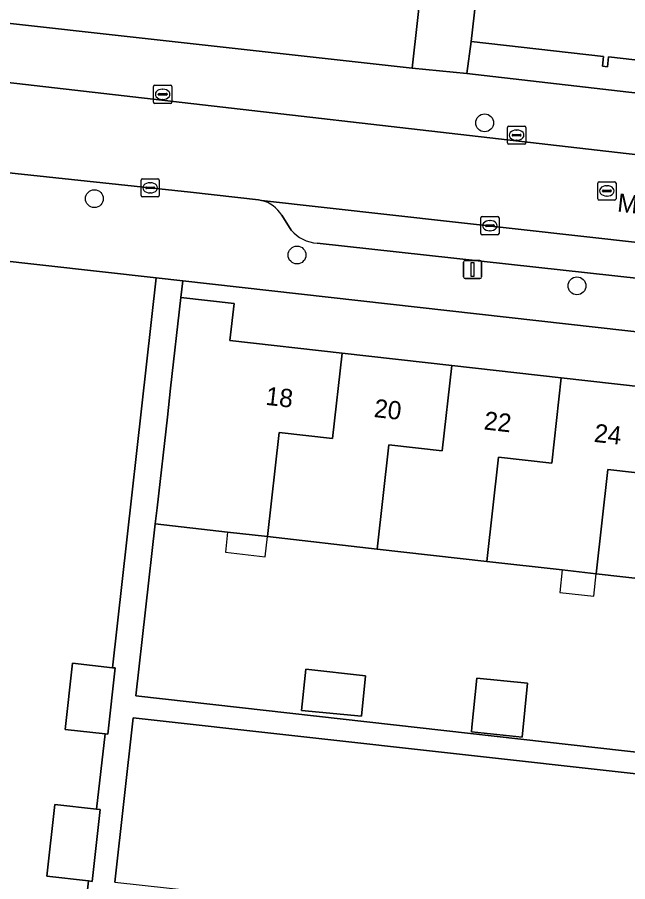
# Model space of a CAD drawing. Extents: x 162082 to 163401, y 388089 to 388636.
# Drawn here: x 162681.06 to 162714.51, y 388132.52 to 388179.87 of the extents above; entities that cross this region are included whole.
import ezdxf

# ---------------------------------------------------------------- set-up
doc = ezdxf.new("R2010")
doc.units = 0
for name, color, linetype in [('IMGEO_Boom', 7, 'Continuous'), ('IMGEO_Erf', 7, 'Continuous'), ('IMGEO_Groenvoorziening', 7, 'Continuous'), ('IMGEO_Kolk', 7, 'Continuous'), ('IMGEO_Lichtmast', 7, 'Continuous'), ('IMGEO_Openbare_ruimte_label', 7, 'Continuous'), ('IMGEO_Pand', 7, 'Continuous'), ('IMGEO_Pand_nummerreeks', 7, 'Continuous'), ('IMGEO_Pand_overbouw', 7, 'Continuous'), ('IMGEO_Parkeervlak_open', 7, 'Continuous'), ('IMGEO_Rijbaan_lokaal_open', 7, 'Continuous'), ('IMGEO_Rioolput', 7, 'Continuous'), ('IMGEO_Voetpad_open', 7, 'Continuous')]:
    doc.layers.add(name, color=color, linetype=linetype)

msp = doc.modelspace()

# ---------------------------------------------------------------- linework, layer by layer
at = {"layer": 'IMGEO_Boom'}
for centre in [(162706.672, 388174.085), (162685.288, 388169.933), (162696.391, 388166.846), (162711.731, 388165.158)]:
    msp.add_circle(centre, 0.489, dxfattribs=at)
at = {"layer": 'IMGEO_Erf'}
for points in [[(162717.454, 388177.245), (162713.462, 388177.697), (162713.4, 388177.152), (162713.124, 388177.183), (162713.185, 388177.719), (162705.936, 388178.541), (162705.689, 388176.792), (162763.406, 388170.138)], [(162684.587, 388129.167), (162684.969, 388132.561), (162682.683, 388132.816), (162683.123, 388136.749), (162685.41, 388136.493), (162685.873, 388140.615), (162683.681, 388140.86), (162684.087, 388144.488), (162686.28, 388144.243), (162688.677, 388165.591), (162664.145, 388168.344)]]:
    msp.add_lwpolyline(points, dxfattribs=at)
for points in [[(162690.136, 388165.428), (162690.025, 388164.519), (162692.944, 388164.19), (162692.715, 388162.163), (162698.866, 388161.469), (162704.866, 388160.792), (162710.866, 388160.116), (162716.866, 388159.439), (162722.866, 388158.762), (162728.866, 388158.085), (162734.867, 388157.408), (162740.866, 388156.732), (162746.866, 388156.055), (162753.017, 388155.361), (162753.371, 388158.332)], [(162724.791, 388148.035), (162718.788, 388148.712), (162712.786, 388149.389), (162710.922, 388149.599), (162706.783, 388150.066), (162700.78, 388150.743), (162694.777, 388151.42), (162692.591, 388151.667), (162688.625, 388152.114), (162687.557, 388142.698), (162750.849, 388135.576), (162751.105, 388137.978), (162751.921, 388145.652), (162749.019, 388145.98), (162748.944, 388145.311), (162743.976, 388145.871), (162742.794, 388146.004), (162736.796, 388146.681), (162730.793, 388147.358)], [(162700.152, 388143.803), (162699.931, 388141.582), (162696.629, 388141.897), (162696.872, 388144.159)], [(162709.02, 388143.398), (162708.726, 388140.444), (162705.952, 388140.72), (162705.978, 388140.981), (162706.246, 388143.674)], [(162686.416, 388132.5), (162692.567, 388131.812), (162698.577, 388131.139), (162704.584, 388130.467), (162710.59, 388129.795), (162716.595, 388129.123), (162722.602, 388128.45), (162728.607, 388127.778), (162734.613, 388127.106), (162740.619, 388126.434), (162741.808, 388126.301), (162746.777, 388125.745), (162749.751, 388125.412), (162750.72, 388134.36), (162750.73, 388134.453), (162687.422, 388141.491)]]:
    msp.add_lwpolyline(points, close=True, dxfattribs=at)
at = {"layer": 'IMGEO_Groenvoorziening'}
msp.add_lwpolyline([(162703.27, 388182.157), (162665.601, 388186.69), (162665.064, 388181.271), (162702.709, 388177.08)], close=True, dxfattribs=at)
at = {"layer": 'IMGEO_Kolk'}
for p, q in [((162688.529, 388175.224), (162688.529, 388176.076)), ((162688.604, 388176.15), (162689.456, 388176.15)), ((162689.53, 388176.076), (162689.53, 388175.224)), ((162688.788, 388175.644), (162688.788, 388175.656)), ((162689.226, 388175.607), (162688.828, 388175.607)), ((162688.831, 388175.693), (162689.229, 388175.693)), ((162689.017, 388175.93), (162689.042, 388175.93)), ((162689.272, 388175.656), (162689.272, 388175.644)), ((162689.456, 388175.15), (162688.604, 388175.15)), ((162689.04, 388175.37), (162689.015, 388175.37)), ((162707.923, 388172.985), (162707.923, 388173.837)), ((162707.998, 388173.911), (162708.85, 388173.911)), ((162708.411, 388173.691), (162708.436, 388173.691)), ((162708.924, 388173.837), (162708.924, 388172.985)), ((162708.182, 388173.405), (162708.182, 388173.417)), ((162708.62, 388173.368), (162708.222, 388173.368)), ((162708.225, 388173.454), (162708.623, 388173.454)), ((162708.666, 388173.417), (162708.666, 388173.405)), ((162708.85, 388172.911), (162707.998, 388172.911)), ((162708.434, 388173.131), (162708.409, 388173.131)), ((162687.845, 388170.1), (162687.845, 388170.952)), ((162687.92, 388171.026), (162688.772, 388171.026)), ((162688.846, 388170.952), (162688.846, 388170.1)), ((162688.104, 388170.52), (162688.104, 388170.532)), ((162688.542, 388170.483), (162688.144, 388170.483)), ((162688.147, 388170.569), (162688.545, 388170.569)), ((162688.333, 388170.806), (162688.358, 388170.806)), ((162688.588, 388170.532), (162688.588, 388170.52)), ((162688.772, 388170.026), (162687.92, 388170.026)), ((162688.356, 388170.246), (162688.331, 388170.246)), ((162706.533, 388168.954), (162707.385, 388168.954)), ((162706.458, 388168.028), (162706.458, 388168.88)), ((162706.717, 388168.448), (162706.717, 388168.46)), ((162706.76, 388168.497), (162707.158, 388168.497)), ((162706.946, 388168.734), (162706.971, 388168.734)), ((162707.201, 388168.46), (162707.201, 388168.448)), ((162707.459, 388168.88), (162707.459, 388168.028)), ((162707.155, 388168.411), (162706.757, 388168.411)), ((162706.969, 388168.174), (162706.944, 388168.174)), ((162707.385, 388167.954), (162706.533, 388167.954))]:
    msp.add_line(p, q, dxfattribs=at)
for points in [[(162688.529, 388175.224), (162688.529, 388176.076)], [(162688.604, 388176.15), (162689.456, 388176.15)], [(162689.53, 388176.076), (162689.53, 388175.224)], [(162689.456, 388175.15), (162688.604, 388175.15)], [(162707.923, 388172.985), (162707.923, 388173.837)], [(162707.998, 388173.911), (162708.85, 388173.911)], [(162708.924, 388173.837), (162708.924, 388172.985)], [(162708.85, 388172.911), (162707.998, 388172.911)], [(162687.845, 388170.1), (162687.845, 388170.952)], [(162687.92, 388171.026), (162688.772, 388171.026)], [(162688.846, 388170.952), (162688.846, 388170.1)], [(162688.772, 388170.026), (162687.92, 388170.026)], [(162706.533, 388168.954), (162707.385, 388168.954)], [(162706.458, 388168.028), (162706.458, 388168.88)], [(162707.459, 388168.88), (162707.459, 388168.028)], [(162707.385, 388167.954), (162706.533, 388167.954)]]:
    msp.add_lwpolyline(points, dxfattribs=at)
for centre, radius, start, end in [((162688.606, 388176.074), 0.0765, 91.552, 178.448), ((162688.606, 388176.074), 0.0765, 91.552, 178.448), ((162689.454, 388176.074), 0.0765, 1.552, 88.448), ((162689.454, 388176.074), 0.0765, 1.552, 88.448), ((162688.828, 388175.653), 0.0403, 85.8775, 175.7526), ((162688.825, 388175.643), 0.0366, 178.938, 274.7102), ((162689.229, 388175.65), 0.043, 264.8664, 352.4533), ((162689.233, 388175.655), 0.0386, 1.7309, 96.639), ((162688.606, 388175.226), 0.0765, 181.552, 268.448), ((162688.606, 388175.226), 0.0765, 181.552, 268.448), ((162689.454, 388175.226), 0.0765, 271.552, 358.448), ((162689.454, 388175.226), 0.0765, 271.552, 358.448), ((162708, 388173.835), 0.0765, 91.552, 178.448), ((162708, 388173.835), 0.0765, 91.552, 178.448), ((162708.848, 388173.835), 0.0765, 1.552, 88.448), ((162708.848, 388173.835), 0.0765, 1.552, 88.448), ((162708.222, 388173.414), 0.0403, 85.8775, 175.7526), ((162708.219, 388173.404), 0.0366, 178.938, 274.7102), ((162708.623, 388173.411), 0.043, 264.8664, 352.4533), ((162708.627, 388173.416), 0.0386, 1.7309, 96.639), ((162708, 388172.987), 0.0765, 181.552, 268.448), ((162708, 388172.987), 0.0765, 181.552, 268.448), ((162708.848, 388172.987), 0.0765, 271.552, 358.448), ((162708.848, 388172.987), 0.0765, 271.552, 358.448), ((162687.922, 388170.95), 0.0765, 91.552, 178.448), ((162687.922, 388170.95), 0.0765, 91.552, 178.448), ((162688.77, 388170.95), 0.0765, 1.552, 88.448), ((162688.77, 388170.95), 0.0765, 1.552, 88.448), ((162688.144, 388170.529), 0.0403, 85.8775, 175.7526), ((162688.141, 388170.519), 0.0366, 178.938, 274.7102), ((162688.545, 388170.526), 0.043, 264.8664, 352.4533), ((162688.549, 388170.531), 0.0386, 1.7309, 96.639), ((162687.922, 388170.102), 0.0765, 181.552, 268.448), ((162687.922, 388170.102), 0.0765, 181.552, 268.448), ((162688.77, 388170.102), 0.0765, 271.552, 358.448), ((162688.77, 388170.102), 0.0765, 271.552, 358.448), ((162706.535, 388168.878), 0.0765, 91.552, 178.448), ((162706.535, 388168.878), 0.0765, 91.552, 178.448), ((162707.383, 388168.878), 0.0765, 1.552, 88.448), ((162707.383, 388168.878), 0.0765, 1.552, 88.448), ((162706.757, 388168.457), 0.0403, 85.8775, 175.7526), ((162707.162, 388168.459), 0.0386, 1.7309, 96.639), ((162706.535, 388168.03), 0.0765, 181.552, 268.448), ((162706.535, 388168.03), 0.0765, 181.552, 268.448), ((162706.754, 388168.447), 0.0366, 178.938, 274.7102), ((162707.158, 388168.454), 0.043, 264.8664, 352.4533), ((162707.383, 388168.03), 0.0765, 271.552, 358.448), ((162707.383, 388168.03), 0.0765, 271.552, 358.448)]:
    msp.add_arc(centre, radius, start, end, dxfattribs=at)
for centre, major_axis, ratio, start_param, end_param in [((162689.016, 388175.65), (-0.387, 0.002), 0.722429, 4.712389, 7.853982), ((162689.041, 388175.65), (-0.39, 0.002), 0.717154, 1.570796, 4.712389), ((162708.41, 388173.411), (-0.387, 0.002), 0.722429, 4.712389, 7.853982), ((162708.435, 388173.411), (-0.39, 0.002), 0.717154, 1.570796, 4.712389), ((162688.332, 388170.526), (-0.387, 0.002), 0.722429, 4.712389, 7.853982), ((162688.357, 388170.526), (-0.39, 0.002), 0.717154, 1.570796, 4.712389), ((162706.945, 388168.454), (-0.387, 0.002), 0.722429, 4.712389, 7.853982), ((162706.97, 388168.454), (-0.39, 0.002), 0.717154, 1.570796, 4.712389)]:
    msp.add_ellipse(centre, major_axis=major_axis, ratio=ratio, start_param=start_param, end_param=end_param, dxfattribs=at)
at = {"layer": 'IMGEO_Lichtmast'}
for p, q in [((162705.512, 388165.653), (162705.512, 388166.453)), ((162705.512, 388166.453), (162705.512, 388165.653)), ((162705.612, 388166.553), (162706.402, 388166.553)), ((162706.402, 388166.553), (162705.612, 388166.553)), ((162706.502, 388166.453), (162706.502, 388165.653)), ((162706.502, 388165.653), (162706.502, 388166.453)), ((162706.402, 388165.553), (162705.612, 388165.553)), ((162705.612, 388165.553), (162706.402, 388165.553))]:
    msp.add_line(p, q, dxfattribs=at)
msp.add_lwpolyline([(162705.932, 388166.428), (162706.082, 388166.428), (162706.082, 388165.678), (162705.932, 388165.678), (162705.932, 388166.428)], dxfattribs=at)
for centre, start, end in [((162705.612, 388166.453), 90, 180), ((162705.612, 388166.453), 90, 180), ((162706.402, 388166.453), 0, 90), ((162706.402, 388166.453), 360, 90), ((162705.612, 388165.653), 180, 270), ((162705.612, 388165.653), 180, 270), ((162706.402, 388165.653), 270, 0), ((162706.402, 388165.653), 270, 0)]:
    msp.add_arc(centre, 0.1, start, end, dxfattribs=at)
at = {"layer": 'IMGEO_Pand'}
for points in [[(162721.626, 388186.43), (162720.225, 388186.589), (162712.643, 388187.449), (162713.504, 388195.041), (162712.849, 388195.115), (162707.88, 388195.679), (162706.975, 388187.702), (162705.936, 388178.541), (162713.185, 388177.719), (162713.124, 388177.183), (162713.4, 388177.152), (162713.462, 388177.697), (162717.454, 388177.245), (162717.537, 388177.981), (162720.421, 388177.654), (162720.279, 388176.403), (162720.485, 388176.38)], [(162698.866, 388161.469), (162692.715, 388162.163), (162692.944, 388164.19), (162690.025, 388164.519), (162689.464, 388159.551), (162689.286, 388157.973), (162688.726, 388153.005), (162688.625, 388152.114), (162692.591, 388151.667), (162694.777, 388151.42), (162695.42, 388157.132), (162698.344, 388156.802)], [(162694.777, 388151.42), (162700.78, 388150.743), (162701.422, 388156.455), (162704.343, 388156.125), (162704.866, 388160.792), (162698.866, 388161.469), (162698.344, 388156.802), (162695.42, 388157.132)], [(162706.783, 388150.066), (162707.425, 388155.777), (162710.344, 388155.448), (162710.866, 388160.116), (162704.866, 388160.792), (162704.343, 388156.125), (162701.422, 388156.455), (162700.78, 388150.743)], [(162713.427, 388155.1), (162716.343, 388154.771), (162716.866, 388159.439), (162710.866, 388160.116), (162710.344, 388155.448), (162707.425, 388155.777), (162706.783, 388150.066), (162710.922, 388149.599), (162712.786, 388149.389)], [(162722.866, 388158.762), (162716.866, 388159.439), (162716.343, 388154.771), (162713.427, 388155.1), (162712.786, 388149.389), (162718.788, 388148.712), (162719.428, 388154.423), (162722.344, 388154.094)], [(162686.28, 388144.243), (162684.087, 388144.488), (162683.681, 388140.86), (162685.873, 388140.615), (162686.025, 388140.598), (162686.43, 388144.226)], [(162700.152, 388143.803), (162696.872, 388144.159), (162696.629, 388141.897), (162699.931, 388141.582)], [(162709.02, 388143.398), (162706.246, 388143.674), (162705.978, 388140.981), (162705.952, 388140.72), (162708.726, 388140.444)], [(162685.41, 388136.493), (162683.123, 388136.749), (162682.683, 388132.816), (162684.969, 388132.561), (162685.164, 388132.539), (162685.604, 388136.471)]]:
    msp.add_lwpolyline(points, close=True, dxfattribs=at)
at = {"layer": 'IMGEO_Pand_overbouw'}
for points in [[(162694.777, 388151.42), (162692.591, 388151.667), (162692.467, 388150.568), (162694.654, 388150.322)], [(162712.786, 388149.389), (162710.922, 388149.599), (162710.784, 388148.366), (162712.648, 388148.157)]]:
    msp.add_lwpolyline(points, close=True, dxfattribs=at)
at = {"layer": 'IMGEO_Parkeervlak_open'}
for points in [[(162753.966, 388163.189), (162694.451, 388169.835)], [(162695.553, 388169.022), (162696.067, 388168.209)], [(162697.497, 388167.497), (162751.077, 388161.612)]]:
    msp.add_lwpolyline(points, dxfattribs=at)
for centre, radius, start, end in [((162694.038, 388168.121), 1.763, 30.727, 76.4369), ((162697.629, 388169.555), 2.062, 220.7387, 266.3237)]:
    msp.add_arc(centre, radius, start, end, dxfattribs=at)
at = {"layer": 'IMGEO_Rijbaan_lokaal_open'}
msp.add_lwpolyline([(162723.437, 388171.392), (162716.658, 388172.147), (162680.392, 388176.308), (162680.066, 388171.399), (162690.562, 388170.28), (162694.289, 388169.866), (162694.451, 388169.835), (162753.966, 388163.189), (162756.651, 388162.831), (162757.203, 388167.636), (162751.96, 388168.22), (162745.54, 388168.934)], close=True, dxfattribs=at)
at = {"layer": 'IMGEO_Rioolput'}
for p, q in [((162712.943, 388170.857), (162713.795, 388170.857)), ((162712.868, 388169.931), (162712.868, 388170.783)), ((162713.127, 388170.351), (162713.127, 388170.363)), ((162713.17, 388170.4), (162713.568, 388170.4)), ((162713.356, 388170.637), (162713.381, 388170.637)), ((162713.611, 388170.363), (162713.611, 388170.351)), ((162713.869, 388170.783), (162713.869, 388169.931)), ((162713.565, 388170.314), (162713.167, 388170.314)), ((162713.379, 388170.077), (162713.354, 388170.077)), ((162713.795, 388169.857), (162712.943, 388169.857))]:
    msp.add_line(p, q, dxfattribs=at)
for points in [[(162712.943, 388170.857), (162713.795, 388170.857)], [(162712.868, 388169.931), (162712.868, 388170.783)], [(162713.869, 388170.783), (162713.869, 388169.931)], [(162713.795, 388169.857), (162712.943, 388169.857)]]:
    msp.add_lwpolyline(points, dxfattribs=at)
for centre, radius, start, end in [((162712.945, 388170.781), 0.0765, 91.552, 178.448), ((162712.945, 388170.781), 0.0765, 91.552, 178.448), ((162713.793, 388170.781), 0.0765, 1.552, 88.448), ((162713.793, 388170.781), 0.0765, 1.552, 88.448), ((162713.167, 388170.36), 0.0403, 85.8775, 175.7526), ((162713.164, 388170.35), 0.0366, 178.938, 274.7102), ((162713.568, 388170.357), 0.043, 264.8664, 352.4533), ((162713.572, 388170.362), 0.0386, 1.7309, 96.639), ((162712.945, 388169.933), 0.0765, 181.552, 268.448), ((162712.945, 388169.933), 0.0765, 181.552, 268.448), ((162713.793, 388169.933), 0.0765, 271.552, 358.448), ((162713.793, 388169.933), 0.0765, 271.552, 358.448)]:
    msp.add_arc(centre, radius, start, end, dxfattribs=at)
for centre, major_axis, ratio, start_param, end_param in [((162713.355, 388170.357), (-0.387, 0.002), 0.722429, 4.712389, 7.853982), ((162713.38, 388170.357), (-0.39, 0.002), 0.717154, 1.570796, 4.712389)]:
    msp.add_ellipse(centre, major_axis=major_axis, ratio=ratio, start_param=start_param, end_param=end_param, dxfattribs=at)
at = {"layer": 'IMGEO_Voetpad_open'}
for points in [[(162729.94, 388342.515), (162721.188, 388343.447), (162720.121, 388331.869), (162719.528, 388326.805), (162714.003, 388278.163), (162713.987, 388278.025), (162710.804, 388250), (162708.484, 388229.124), (162708.41, 388228.518), (162704.239, 388190.913), (162703.915, 388187.998), (162703.27, 388182.157), (162702.709, 388177.08), (162705.689, 388176.792), (162705.936, 388178.541), (162706.975, 388187.702), (162707.88, 388195.679), (162708.768, 388202.91), (162709.83, 388212.61), (162710.107, 388214.707), (162711.489, 388227.332), (162713.938, 388250), (162717.461, 388280.321), (162722.517, 388279.851)], [(162705.689, 388176.792), (162702.709, 388177.08), (162665.064, 388181.271), (162664.665, 388177.732)], [(162667.962, 388177.734), (162677.587, 388176.629), (162680.392, 388176.308), (162716.658, 388172.147), (162723.437, 388171.392), (162745.54, 388168.934), (162751.96, 388168.22), (162757.203, 388167.636), (162760.046, 388167.375), (162760.642, 388167.307)], [(162766.884, 388169.752), (162763.406, 388170.138), (162705.689, 388176.792)], [(162694.451, 388169.835), (162694.289, 388169.866), (162690.562, 388170.28), (162680.066, 388171.399), (162677.203, 388171.704), (162666.796, 388172.923)], [(162696.067, 388168.209), (162695.553, 388169.022)], [(162664.145, 388168.344), (162688.677, 388165.591), (162690.136, 388165.428), (162753.371, 388158.332), (162756.524, 388157.89), (162756.874, 388157.847), (162756.854, 388157.711), (162757.874, 388157.615), (162757.9, 388157.737), (162772.131, 388156.161), (162773.046, 388164.918), (162773.053, 388165.285)], [(162751.077, 388161.612), (162697.497, 388167.497)], [(162750.849, 388135.576), (162687.557, 388142.698), (162688.625, 388152.114), (162688.726, 388153.005), (162689.286, 388157.973), (162689.464, 388159.551), (162690.025, 388164.519), (162690.136, 388165.428), (162688.677, 388165.591), (162686.28, 388144.243), (162686.43, 388144.226), (162686.025, 388140.598), (162685.873, 388140.615), (162685.41, 388136.493), (162685.604, 388136.471), (162685.164, 388132.539), (162684.969, 388132.561), (162684.587, 388129.167)], [(162686.416, 388132.5), (162687.422, 388141.491), (162750.73, 388134.453)]]:
    msp.add_lwpolyline(points, dxfattribs=at)
for centre, radius, start, end in [((162694.038, 388168.121), 1.763, 30.727, 76.4369), ((162697.629, 388169.555), 2.062, 220.7387, 266.3237)]:
    msp.add_arc(centre, radius, start, end, dxfattribs=at)

# ---------------------------------------------------------------- texts
at = {"layer": 'IMGEO_Openbare_ruimte_label'}
msp.add_text('Mantualaan', height=1, rotation=353.6282, dxfattribs=at).set_placement((162713.907, 388169.232))
at = {"layer": 'IMGEO_Pand_nummerreeks'}
for s, rotation, p in [('18', 353.5657, (162694.635, 388158.645)), ('20', 353.5643, (162700.574, 388157.976)), ('22', 353.5643, (162706.598, 388157.296)), ('24', 353.5657, (162712.632, 388156.616))]:
    msp.add_text(s, height=1, rotation=rotation, dxfattribs=at).set_placement(p)

doc.saveas('drawing.dxf')
